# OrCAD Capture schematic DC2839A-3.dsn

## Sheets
1 PAGE2: size A; note: HIGH VOLTAGE, HIGH SIDE CURRENT AND VOLTAGE SENSE
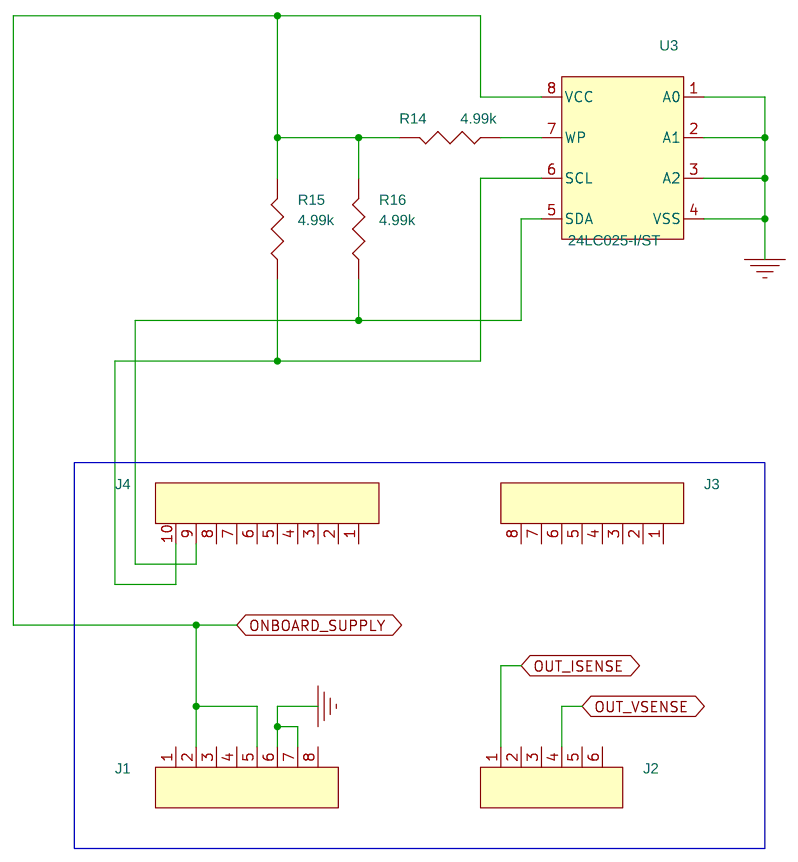
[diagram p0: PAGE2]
2 PAGE1: size Custom
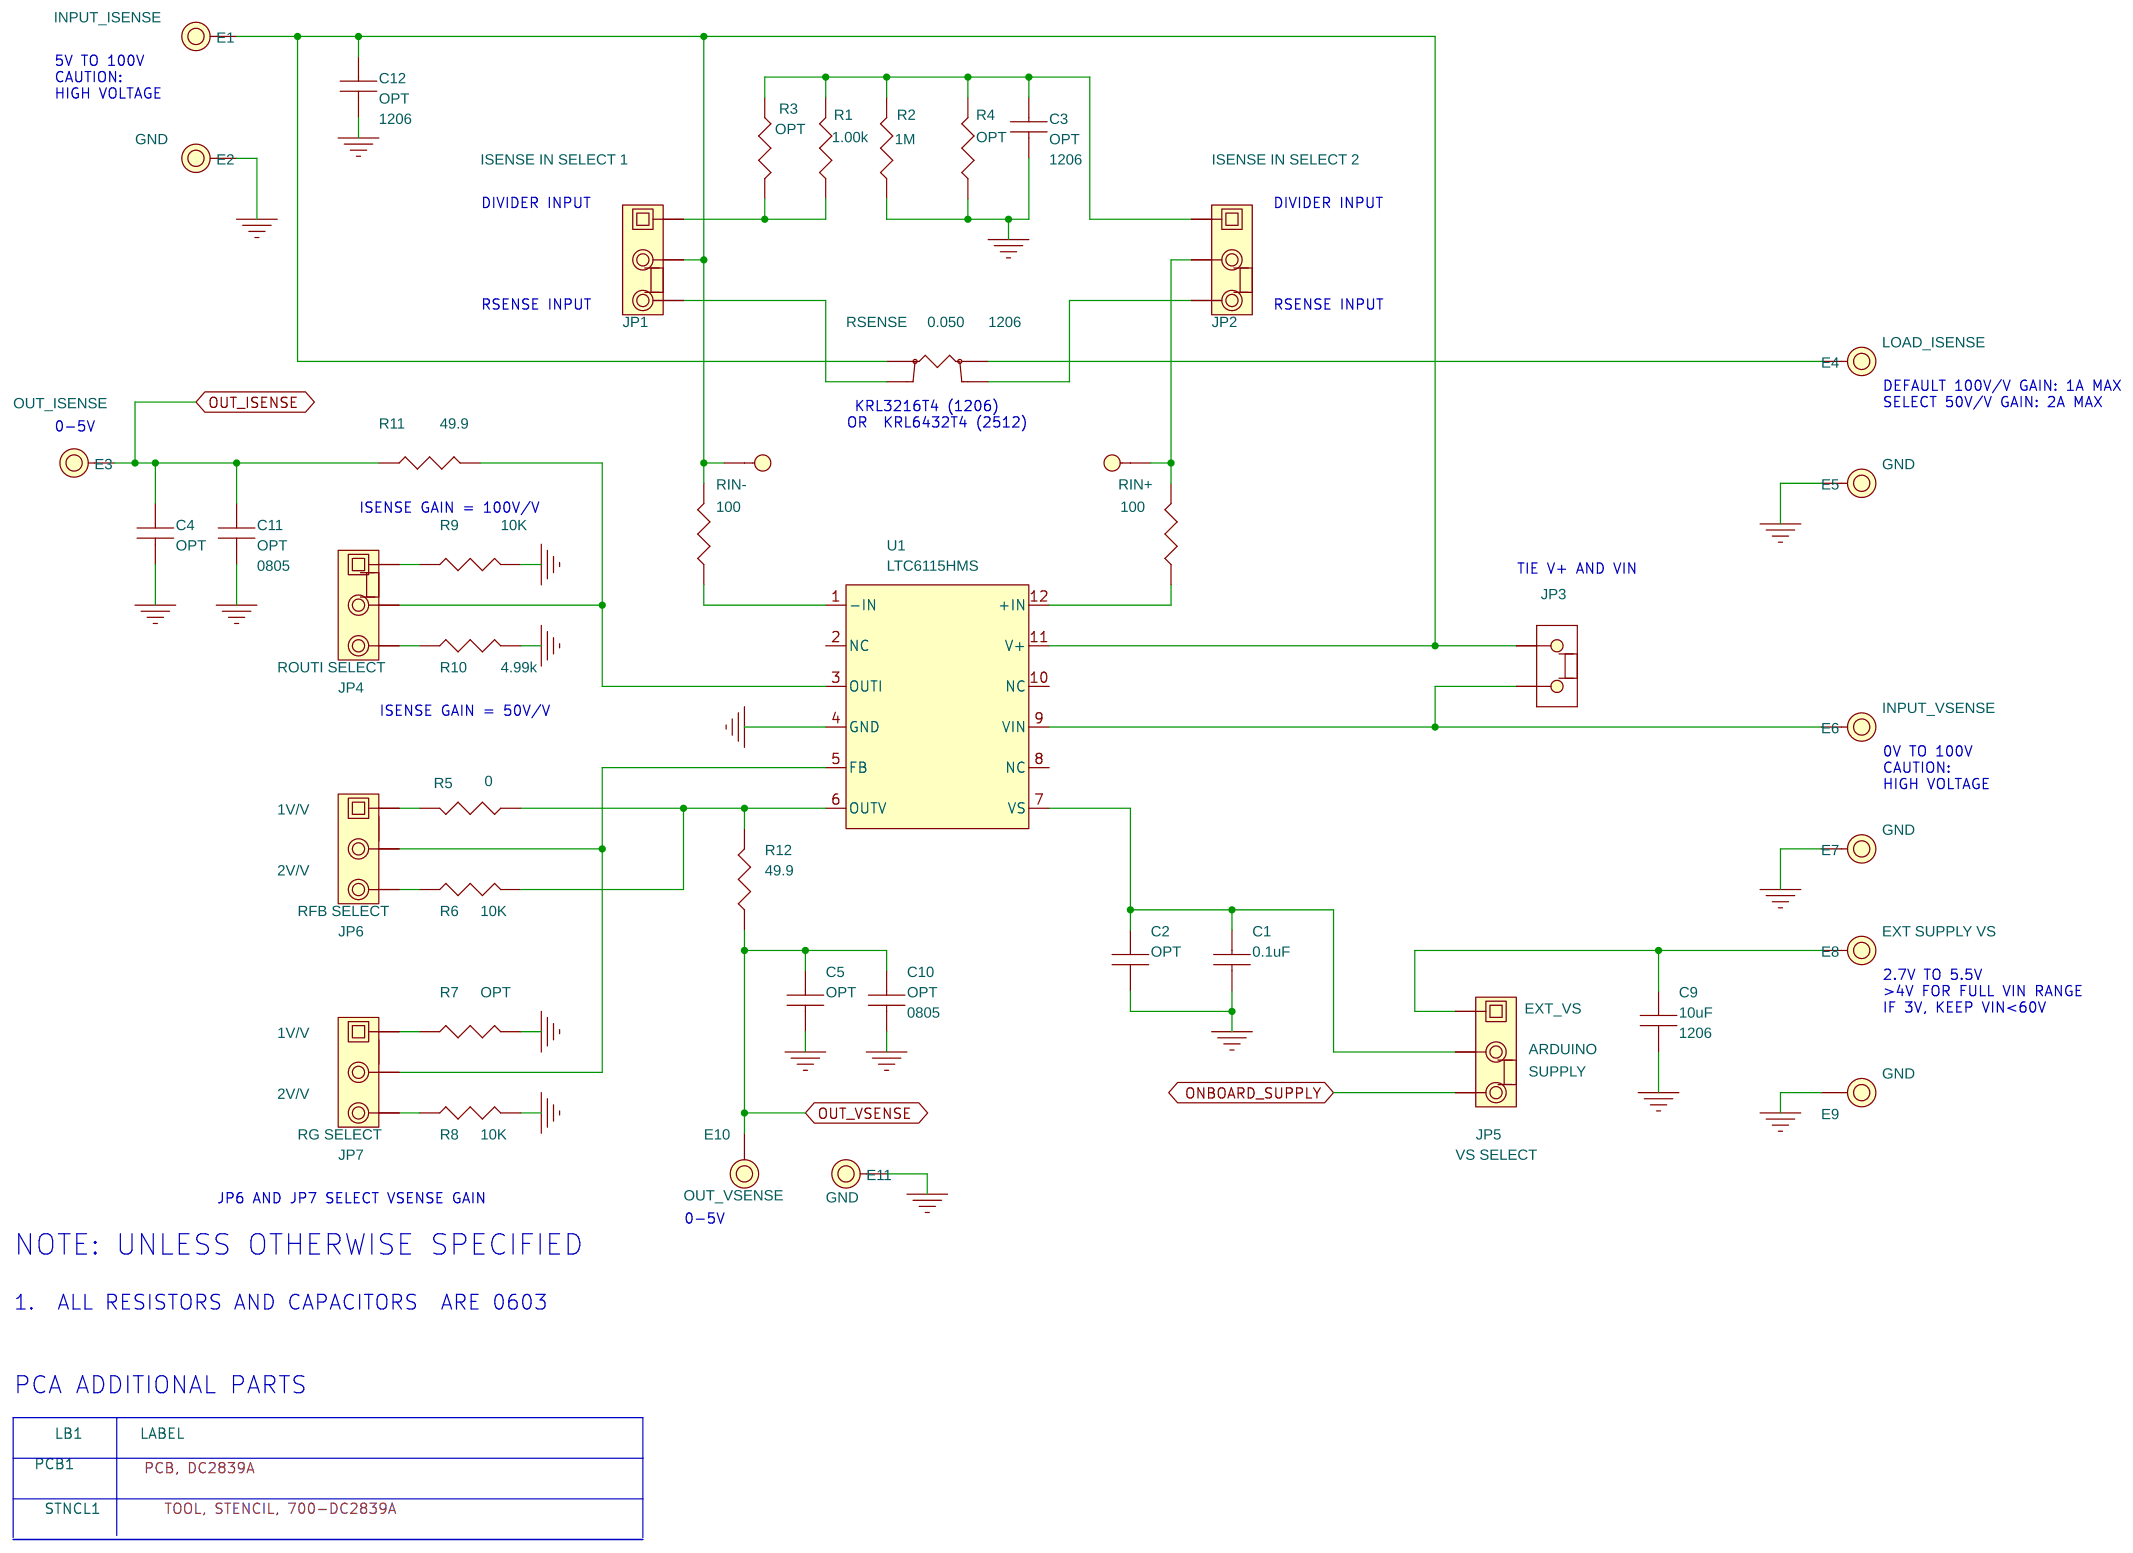
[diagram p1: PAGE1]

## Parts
sheet PAGE1
C1  0.1uF  [CC0603N]
C2  OPT  [CC0603N]
C3  OPT  [CC1206N]
C4  OPT  [CC0603N]
C5  OPT  [CC0603N]
C9  10uF  [CC1206N]
C10  OPT  [CC0805N]
C11  OPT  [CC0805N]
C12  OPT  [CC1206N]
E1  TEST POINT  [MILLMAX2501]
E2  TEST POINT  [MILLMAX2501]
E3  TEST POINT  [MILLMAX2501]
E4  TEST POINT  [MILLMAX2501]
E5  TEST POINT  [MILLMAX2501]
E6  TEST POINT  [MILLMAX2501]
E7  TEST POINT  [MILLMAX2501]
E8  TEST POINT  [MILLMAX2501]
E9  TEST POINT  [MILLMAX2501]
E10  TEST POINT  [MILLMAX2501]
E11  TEST POINT  [MILLMAX2501]
JP1  HDR.  [HD1X3-079]
JP2  HDR.  [HD1X3-079]
JP3  HDR.  [HD1X2-079]
JP4  HDR.  [HD1X3-079]
JP5  HDR.  [HD1X3-079]
JP6  HDR.  [HD1X3-079]
JP7  HDR.  [HD1X3-079]
LB1  LABEL  [895-0154_REV01]
PCB1  PCB, DC2839A
R1  1.00k  [CR0603N]
R2  1M  [CR0603N]
R3  OPT  [CR0603N]
R4  OPT  [CR0603N]
R5  0  [CR0603N]
R6  10K  [CR0603N]
R7  OPT  [CR0603N]
R8  10K  [CR0603N]
R9  10K  [CR0603N]
R10  4.99k  [CR0603N]
R11  49.9  [CR0603N]
R12  49.9  [CR0603N]
RIN+  100  [CR0603N]
RIN-  100  [CR0603N]
RSENSE  0.050  [SUSUMU-KRL3216T4]
STNCL1  TOOL, STENCIL, 700-DC2839A
TP1  TEST POINT, COPPER PAD 100 X 25  [TEST]
TP2  TEST POINT, COPPER PAD 100 X 25  [TEST]
U1  LTC6115HMS  [LTC-MS-12-1668]
XJP1  SHUNT
XJP2  SHUNT
XJP3  SHUNT
XJP4  SHUNT
XJP5  SHUNT
XJP6  SHUNT
XJP7  SHUNT
sheet PAGE2
J1  HDR  [HD1X8-100]
J2  HDR.  [HD1X6-100]
J3  HDR  [HD1X8-100]
J4  HDR  [HD1X10-100]
R14  4.99k  [CR0603N]
R15  4.99k  [CR0603N]
R16  4.99k  [CR0603N]
U3  24LC025-I/ST  [MICROCHIP-TSSOP-8]

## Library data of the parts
C1 = CAP: CAP.,0.1uF,X7R,16V,10%,0603; CLASS: DISCRETE; Dielectric Type: X7R; FPLIST: CC0603N,CC0603L,CC0603M; Manufacturer: AVX; Manufacturer PN: 0603YC104KAT2A; PART_NUMBER: 150-0164; Package Size: 0603; Package Type: SMD; Rated Voltage: 16V; Tolerance: 10%
C2 C4 C5 = CAP: CAP., OPTION, 0603; CLASS: DISCRETE; FPLIST: CC0603N,CC0603L,CC0603M; PART_NUMBER: 150-3038; Package Size: 0603; Package Type: SMD
C3 C12 = CAP: CAP., OPTION, 1206; CLASS: DISCRETE; FPLIST: CC1206N,CC1206L,CC1206M; PART_NUMBER: 150-3160; Package Size: 1206; Package Type: SMD
C9 = CAP: CAP.,10uF,X7R,25V,10%,1206,AEC-Q200; CLASS: DISCRETE; Dielectric Type: X7R; FPLIST: CC1206N,CC1206L,CC1206M; Manufacturer: KEMET; Manufacturer PN: C1206C106K3RACAUTO; PART_NUMBER: 150-0503; Package Size: 1206; Rated Voltage: 25V; Tolerance: 10%
C10 C11 = CAP: CAP., OPTION, 0805; CLASS: DISCRETE; FPLIST: CC0805N,CC0805L,CC0805M; PART_NUMBER: 150-3036; Package Size: 0805; Package Type: SMD
E1 = TESTPOINT_.219_MILL-MAX_2501: TEST POINT,TURRET,0.094",MTG. HOLE; 1: INPUT_ISENSE; CLASS: IO; FPLIST: MILLMAX2501,MILLMAX2501_ALT1; Manufacturer: MILL-MAX; Manufacturer PN: 2501-2-00-80-00-00-07-0; PART_NUMBER: 260-0003
E2 E5 E7 E9 E11 = TESTPOINT_.219_MILL-MAX_2501: TEST POINT,TURRET,0.094",MTG. HOLE; 1: GND; CLASS: IO; FPLIST: MILLMAX2501,MILLMAX2501_ALT1; Manufacturer: MILL-MAX; Manufacturer PN: 2501-2-00-80-00-00-07-0; PART_NUMBER: 260-0003
E3 = TESTPOINT_.219_MILL-MAX_2501: TEST POINT,TURRET,0.094",MTG. HOLE; 1: OUT_ISENSE; CLASS: IO; FPLIST: MILLMAX2501,MILLMAX2501_ALT1; Manufacturer: MILL-MAX; Manufacturer PN: 2501-2-00-80-00-00-07-0; PART_NUMBER: 260-0003
E4 = TESTPOINT_.219_MILL-MAX_2501: TEST POINT,TURRET,0.094",MTG. HOLE; 1: LOAD_ISENSE; CLASS: IO; FPLIST: MILLMAX2501,MILLMAX2501_ALT1; Manufacturer: MILL-MAX; Manufacturer PN: 2501-2-00-80-00-00-07-0; PART_NUMBER: 260-0003
E6 = TESTPOINT_.219_MILL-MAX_2501: TEST POINT,TURRET,0.094",MTG. HOLE; 1: INPUT_VSENSE; CLASS: IO; FPLIST: MILLMAX2501,MILLMAX2501_ALT1; Manufacturer: MILL-MAX; Manufacturer PN: 2501-2-00-80-00-00-07-0; PART_NUMBER: 260-0003
E8 = TESTPOINT_.219_MILL-MAX_2501: TEST POINT,TURRET,0.094",MTG. HOLE; 1: EXT SUPPLY VS; CLASS: IO; FPLIST: MILLMAX2501,MILLMAX2501_ALT1; Manufacturer: MILL-MAX; Manufacturer PN: 2501-2-00-80-00-00-07-0; PART_NUMBER: 260-0003
E10 = TESTPOINT_.219_MILL-MAX_2501: TEST POINT,TURRET,0.094",MTG. HOLE; 1: OUT_VSENSE; CLASS: IO; FPLIST: MILLMAX2501,MILLMAX2501_ALT1; Manufacturer: MILL-MAX; Manufacturer PN: 2501-2-00-80-00-00-07-0; PART_NUMBER: 260-0003
JP1 = 1X3_A: CONN.,HDR.,MALE,1x3,2mm,THT, STR,NO SUBS. ALLOWED; 12th Part Field: ISENSE IN SELECT 1; CLASS: IO; Manufacturer: SAMTEC; Manufacturer PN: TMM-103-02-L-S; PART_NUMBER: 250-0638
JP2 = 1X3_A: CONN.,HDR.,MALE,1x3,2mm,THT, STR,NO SUBS. ALLOWED; 12th Part Field: ISENSE IN SELECT 2; CLASS: IO; Manufacturer: SAMTEC; Manufacturer PN: TMM-103-02-L-S; PART_NUMBER: 250-0638
JP3 = HDR1X2: CONN.,HDR.,MALE,1x2,2mm,THT, STR; CLASS: IO; Manufacturer: SULLINS CONNECTOR SOLUTIONS; Manufacturer PN: NRPN021PAEN-RC; PART_NUMBER: 250-0449
JP4 = 1X3_A: CONN.,HDR.,MALE,1x3,2mm,THT, STR,NO SUBS. ALLOWED; 12th Part Field: ROUTI SELECT; CLASS: IO; Manufacturer: SAMTEC; Manufacturer PN: TMM-103-02-L-S; PART_NUMBER: 250-0638
JP5 = 1X3_A: CONN.,HDR.,MALE,1x3,2mm,THT, STR,NO SUBS. ALLOWED; 10th Part Field: ARDUINO; 11th Part Field: SUPPLY; 12th Part Field: VS SELECT; 9th Part Field: EXT_VS; CLASS: IO; Manufacturer: SAMTEC; Manufacturer PN: TMM-103-02-L-S; PART_NUMBER: 250-0638
JP6 = 1X3_A: CONN.,HDR.,MALE,1x3,2mm,THT, STR,NO SUBS. ALLOWED; 10th Part Field: 2V/V; 12th Part Field: RFB SELECT; 9th Part Field: 1V/V; CLASS: IO; Manufacturer: SAMTEC; Manufacturer PN: TMM-103-02-L-S; PART_NUMBER: 250-0638
JP7 = 1X3_A: CONN.,HDR.,MALE,1x3,2mm,THT, STR,NO SUBS. ALLOWED; 10th Part Field: 2V/V; 12th Part Field: RG SELECT; 9th Part Field: 1V/V; CLASS: IO; Manufacturer: SAMTEC; Manufacturer PN: TMM-103-02-L-S; PART_NUMBER: 250-0638
LB1 = BLANK_LABEL: LABEL SPEC, DEMO BOARD SERIAL NUMBER; Manufacturer: BRADY; Manufacturer PN: THT-96-717-10; PART_NUMBER: 895-0154
PCB1 = BLANK_PCB_PART: CLASS: DISCRETE; Manufacturer: EAGLE TECH. INC.; Manufacturer PN: 600-DC2839A; PART_NUMBER: 600-DC2839A
R1 = RES: RES.,1.00k OHMS,1%,1/10W,0603; CLASS: DISCRETE; FPLIST: CR0603N,CR0603L,CR0603M; Manufacturer: VISHAY; Manufacturer PN: CRCW06031K00FKEA; PART_NUMBER: 100-2309; Package Size: 0603; Rated Power: 1/10W; Temperature Coefficient: 100ppm/C; Tolerance: 1%
R2 = RES: RES.,AEC-Q200,1M OHM,1%,1/10W,0603; CLASS: DISCRETE; FPLIST: CR0603N,CR0603L,CR0603M; Manufacturer: NIC; Manufacturer PN: NRC06F1004TRF; PART_NUMBER: 100-0119; Package Size: 0603; Rated Power: 1/10W; Temperature Coefficient: 100ppm/C; Tolerance: 1%
R3 R4 R7 = RES: RES., OPTION, 0603; CLASS: DISCRETE; FPLIST: CR0603N,CR0603L,CR0603M; PART_NUMBER: 100-2374; Package Size: 0603
R5 = RES: RES.,AEC-Q200,0 OHMS,1%,0603; CLASS: DISCRETE; FPLIST: CR0603N,CR0603L,CR0603M; Manufacturer: KOA SPEER; Manufacturer PN: RK73Z1JTTDD; PART_NUMBER: 100-0596; Package Size: 0603; Tolerance: 1%
R6 R8 R9 = RES: RES.,AEC-Q200,10K OHMS,1%,1/10W,0603; CLASS: DISCRETE; FPLIST: CR0603N,CR0603L,CR0603M; Manufacturer: PANASONIC; Manufacturer PN: ERJ3EKF1002V; PART_NUMBER: 100-0602; Package Size: 0603; Rated Power: 1/10W; Temperature Coefficient: 100PPM; Tolerance: 1%
R10 R14-R16 = RES: RES.,4.99K OHMS,0.1%,1/10W,0603; CLASS: DISCRETE; FPLIST: CR0603N,CR0603L,CR0603M; Manufacturer: VISHAY; Manufacturer PN: TNPW06034K99BEEA; PART_NUMBER: 100-0749; Package Size: 0603; Rated Power: 1/10W; Temperature Coefficient: +/-25PPM; Tolerance: 0.1%
R11 = RES: RES.,49.9 OHMS,1%,1/10W,0603; CLASS: DISCRETE; FPLIST: CR0603N,CR0603L,CR0603M; Manufacturer: PANASONIC; Manufacturer PN: ERJ3EKF49R9V; PART_NUMBER: 100-0115; Package Size: 0603; Rated Power: 1/10W; Temperature Coefficient: +/-100ppm; Tolerance: 1%
R12 = RES: RES.,AEC-Q200,49.9 OHMS,1%,1/10W,0603; CLASS: DISCRETE; FPLIST: CR0603N,CR0603L,CR0603M; Manufacturer: VISHAY; Manufacturer PN: CRCW060349R9FKEA; PART_NUMBER: 100-0167; Package Size: 0603; Rated Power: 1/10W; Temperature Coefficient: 100ppm; Tolerance: 1%
RIN+ RIN- = RES: RES.,AEC-Q200,100 OHMS,1%,1/10W,0603; CLASS: DISCRETE; FPLIST: CR0603N,CR0603L,CR0603M; Manufacturer: PANASONIC; Manufacturer PN: ERJ3EKF1000V; PART_NUMBER: 100-0609; Package Size: 0603; Rated Power: 1/10W; Temperature Coefficient: 100PPM; Tolerance: 1%
RSENSE = RES_4_PIN_6: RES.,AEC-Q200,4-TERM,LONG SIDE,0.050 OHMS,1%,1W,1206; CLASS: DISCRETE; Manufacturer: SUSUMU; Manufacturer PN: KRL3216T4-M-R050-F; PART_NUMBER: 100-2004; Package Size: 1206; Rated Power: 1W; Temperature Coefficient: +/-50ppm; Tolerance: 1%
STNCL1 = BLANK_STENCIL_PART: CLASS: DISCRETE; Manufacturer: LINEAR TECH.; Manufacturer PN: 830-DC2839A; PART_NUMBER: 830-DC2839A
TP1 TP2 = TEST_POINT,_COPPER_PAD_100_X_25: PCB PAD, 100
U1 = LTC6115-MS: IC,HIGH VOLTAGE,HIGH SIDE CURRENT AND HIGH SENSE; CLASS: IC; Manufacturer: LINEAR TECH.; Manufacturer PN: LTC6115HMS#PBF; PART_NUMBER: LTC6115HMS#PBF; Package Size: MS12; Package Type: HIGH SIDE CURRENT
XJP1-XJP7 = SHUNT_2MM_B: CONN.,SHUNT,FEMALE,2-POS,2mm; CLASS: IO; Manufacturer: SAMTEC; Manufacturer PN: 2SN-BK-G; PART_NUMBER: 250-0419
J1 = CON8: CONN.,HDR,MALE,1x8,2.54mm,STR, THT; 1: GND; 2: 3.3V; 3: POWER; CLASS: IO; Manufacturer: SAMTEC; Manufacturer PN: TSW-108-07-L-S; PART_NUMBER: 250-0573
J2 = CON6: CONN.,HDR.,MALE,1x6,2.54mm,THT, STR; 1: AO; CLASS: IO; Manufacturer: SAMTEC; Manufacturer PN: TSW-106-07-L-S; PART_NUMBER: 250-0537
J3 = CON8: CONN.,HDR,MALE,1x8,2.54mm,STR, THT; CLASS: IO; Manufacturer: SAMTEC; Manufacturer PN: TSW-108-07-L-S; PART_NUMBER: 250-0573
J4 = CON10_ALT: CONN.,HDR,MALE,1x10,2.54mm,THT,STR; CLASS: IO; Manufacturer: SAMTEC; Manufacturer PN: TSW-110-07-L-S; PART_NUMBER: 250-0606
U3 = 24LC025-I_ST_TSSOP-8: IC, MEMORY,EEPROM,2Kb (256x8),TSSOP-8,400kHz; CLASS: IC; Manufacturer: Microchip; PART_NUMBER: 380-0087; Package Size: TSSOP-8; Package Type: TSSOP-8

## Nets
GND_POWER: C1.2 C2.2 C3.2 C4.2 C5.2 C9.2 C10.2 C11.2 C12.2 E2.1 E5.1 E7.1 E9.1 E11.1 J1.6 J1.7 R2.2 R4.1 R7.1 R8.2 R9.2 R10.2 U1.4(GND) U3.1(A0) U3.2(A1) U3.3(A2) U3.4(VSS)
ONBOARD_SUPPLY: J1.2 J1.5 JP5.3 R14.2 R15.2 R16.2 U3.8(VCC)
OUT_ISENSE: C4.1 C11.1 E3.1 J2.1 R11.1
OUT_VSENSE: C5.1 C10.1 E10.1 J2.4 R12.1
N00457: C1.1 C2.1 JP5.2 U1.7(VS)
N00462: C12.1 E1.1 JP1.2 JP3.1 RIN-.2 RSENSE.2 TP1.1(A) U1.11(V+)
N00486: RIN+.1 U1.12(+IN)
N08198: E4.1 RSENSE.1
N09518: E6.1 JP3.2 U1.9(VIN)
N10069: R5.1 R6.2 R12.2 U1.6(OUTV)
N15310: RIN-.1 U1.1(-IN)
N15319: JP4.2 R11.2 U1.3(OUTI)
N17515: JP4.3 R10.1
N17519: JP4.1 R9.1
N18209: JP6.2 JP7.2 U1.5(FB)
N22406: C9.1 E8.1 JP5.1
N24570: J4.9 R16.1 U3.5(SDA)
N24601: J4.10 R15.1 U3.6(SCL)
N24707: R14.1 U3.7(WP)
N42012: JP1.3 RSENSE.4
N52945: JP1.1 R1.2 R3.2
N52979: JP2.2 RIN+.2 TP2.1(A)
N53131: JP2.3 RSENSE.3
N61212: JP6.1 R5.2
N61214: JP6.3 R6.1
N62705: C3.1 JP2.1 R1.1 R2.1 R3.1 R4.2
N64324: JP7.1 R7.2
N64356: JP7.3 R8.1

Not connected (* = marked no-connect by the designer): J1 1 3 4 8; J2 2 3 5 6; J3 1 2 3 4 5 6 7 8; J4 1 2 3 4 5 6 7 8; U1 2(NC) 8(NC) 10(NC)

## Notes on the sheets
sheet 2
- 5V TO 100V
  CAUTION:
  HIGH VOLTAGE
- DIVIDER INPUT
- DIVIDER INPUT
- RSENSE INPUT
- RSENSE INPUT
- DEFAULT 100V/V GAIN: 1A MAX
  SELECT 50V/V GAIN: 2A MAX
- KRL3216T4 (1206)
  OR  KRL6432T4 (2512)
- 0-5V
- ISENSE GAIN = 100V/V
- TIE V+ AND VIN
- ISENSE GAIN = 50V/V
- 0V TO 100V
  CAUTION:
  HIGH VOLTAGE
- 2.7V TO 5.5V
  >4V FOR FULL VIN RANGE
  IF 3V, KEEP VIN<60V
- JP6 AND JP7 SELECT VSENSE GAIN
- 0-5V
- NOTE: UNLESS OTHERWISE SPECIFIED
- 1.  ALL RESISTORS AND CAPACITORS  ARE 0603
- PCA ADDITIONAL PARTS
